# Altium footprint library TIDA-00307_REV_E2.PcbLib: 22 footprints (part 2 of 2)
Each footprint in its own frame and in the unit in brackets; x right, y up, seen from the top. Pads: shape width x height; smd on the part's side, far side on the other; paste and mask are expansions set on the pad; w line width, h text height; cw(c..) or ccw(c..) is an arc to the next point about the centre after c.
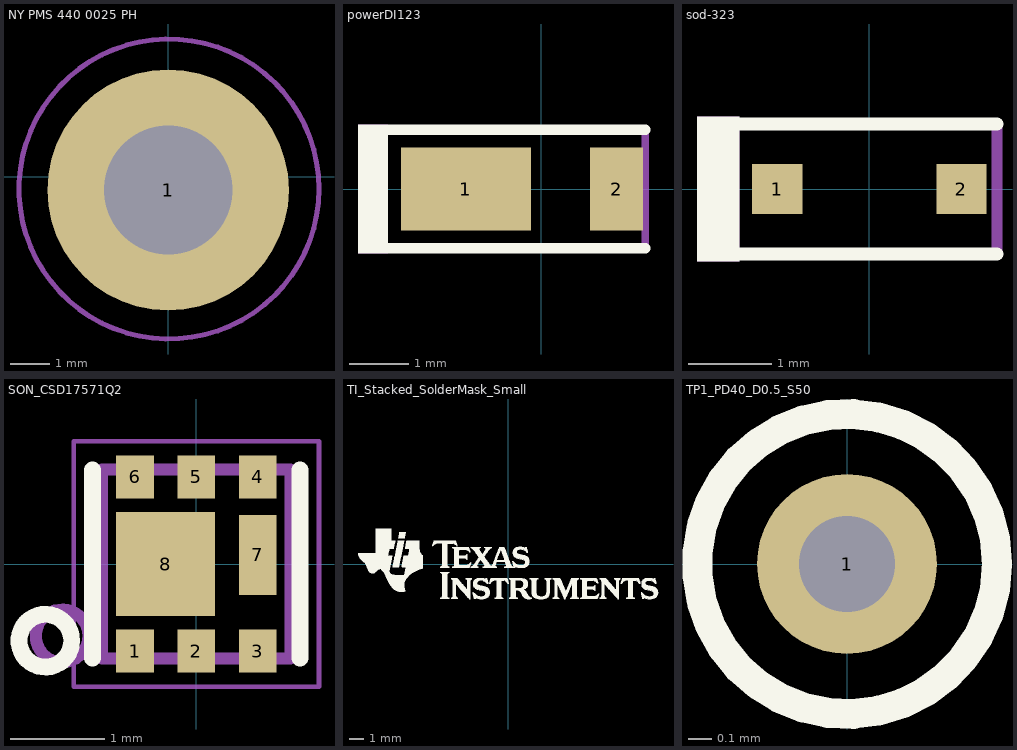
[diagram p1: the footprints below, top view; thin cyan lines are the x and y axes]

## NY PMS 440 0025 PH [mil] "4-40 nylon screw and mounting hole"
height 75
pads (1):
  round 240 hole 128: 1(0,-13)
Mechanical 5:
  circle w5: c0.84,-12 r149.16
  text ".Designator" at -60,-20 h30
3D body: height 106, standoff -344, extent -130,-129.93 129.77,129.93

## powerDI123 [mm] "Diodes Inc recommended land pattern, document number DS30628 Rev. 6-2"
height 1
pads (2):
  rect 2.2x1.4 smd: 1(-1.275,0)
  rect 0.9x1.4 smd: 2(1.275,0)
Top Overlay:
  rectangle: -3.099,-1.092 -2.591,1.092
  lines w0.178: -2.946,-1.003 1.759,-1.003 ; -2.946,1.003 1.759,1.003
Mechanical 5:
  rectangle: -3.099,-1.092 -2.591,1.092
  lines w0.127: -2.946,-1.003 1.759,-1.003 1.759,1.003 -2.946,1.003
  text ".Designator" at -1.6,-0.406 h0.76
3D body: height 1, standoff 0, extent -2.375,-0.965 1.525,0.965

## sod-323 [mm] "NXP recommended land pattern"
height 1.1
pads (2):
  rect 0.6x0.6 smd: 1(-1.1,0) 2(1.1,0)
Top Overlay:
  rectangle: -2.057,-0.864 -1.549,0.864
  lines w0.152: -1.803,-0.775 0.1,-0.775 1.525,-0.775 ; -1.803,0.775 0.1,0.775 1.525,0.775
Mechanical 5:
  rectangle: -2.057,-0.864 -1.549,0.864
  lines w0.127: -1.803,-0.775 0.1,-0.775 1.525,-0.775 1.525,0.775 0.1,0.775 -1.803,0.775
  text ".Designator" at 0.914,0.432 h0.76
3D body: height 1.1, standoff 0, extent -1.3,-0.675 1.3,0.675

## SON_CSD17571Q2 [mm] "SON, MOSFET, N-CH, 30V, 22A, SON 2X2 MM"
height 0.85
pads (8):
  rect 0.4x0.455 smd mask+0.038: 1(-0.65,-0.923) 2(0,-0.923) 5(0,0.923) 6(-0.65,0.923)
  rect 0.4x0.455 smd: 3(0.65,-0.923) 4(0.65,0.923)
  rect 0.4x0.85 smd mask+0.038: 7(0.65,0.096)
  rect 1.05x1.1 smd mask+0.038: 8(-0.325,0)
Top Overlay:
  circle w0.178: c-1.6,-0.813 r0.279
  lines w0.178: -1.1,-1 -1.1,1 ; 1.1,-1 1.1,1
  text ".Designator" at 2.413,-0.457 h0.89
Mechanical 5:
  circle w0.127: c-1.422,-0.762 r0.279
  lines w0.127: -1,-1 1,-1 1,1 -1,1 -1,-1
  text ".Designator" at 0.356,-0.635 h0.76
Mechanical 15:
  lines w0.05: -1.3,-1.3 -1.3,1.3 1.3,1.3 1.3,-1.3 -1.3,-1.3
3D body: height 0.85, standoff 0, extent -1,-1 1,0.975

## TI_Stacked_SolderMask_Small [mm]
height 1.905
Top Overlay:
  drawing of 18 lines, arcs and shapes, not listed

## TP1_PD40_D0.5_S50 [mil]
height 1.4
pads (1):
  round 30 hole 16: 1(0,0)
Top Overlay:
  circle w5: c0,0 r25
